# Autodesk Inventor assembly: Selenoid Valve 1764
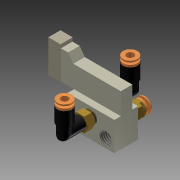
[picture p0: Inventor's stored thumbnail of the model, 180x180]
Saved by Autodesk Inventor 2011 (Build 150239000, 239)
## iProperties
Created: 2010-02
Part Number: Selenoid Valve 1764
Document SubType Name: Assembly
Designer: jgehrig
Author: jgehrig
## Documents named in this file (5)
- R:\CAD Archives\Pneumatics\Seloniod 1764\Selenoid Valve 1764.iam
- R:\CAD Archives\Pneumatics\Seloniod 1764\Selenoid Base 1764.ipt
- R:\CAD Archives\Pneumatics\Seloniod 1764\Selenoid Part 1764.ipt
- R:\CAD Archives\Pneumatics\Seloniod 1764\Pneumatic Screw 1764\Pneumatic Screw 1764.iam
- R:\CAD Archives\Pneumatics\Seloniod 1764\Pnewmatics Bend Piece 1764\Pneumatic Bend Piece 1764.iam
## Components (5 placed, 4 different names)
1. Selenoid Base 1764:1 — Flush:1, Mate:1, Flush:2, Insert:3, Insert:4, Insert:5
2. Selenoid Part 1764:1 — Flush:1, Mate:1, Flush:2, Angle:4, Angle:5
3. Pneumatic Screw 1764:1 [sub-assembly] — Insert:3
4. Pneumatic Bend Piece 1764:1 [sub-assembly] — Insert:5, Angle:4
5. Pneumatic Bend Piece 1764:2 [sub-assembly] — Insert:4, Angle:5
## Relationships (8: Insert 3, Flush 2, Angle 2, Mate 1)
- Flush:1: Selenoid Base 1764:1 ↔ Selenoid Part 1764:1
- Mate:1: Selenoid Base 1764:1 ↔ Selenoid Part 1764:1
- Flush:2: Selenoid Base 1764:1 ↔ Selenoid Part 1764:1
- Insert:3: Selenoid Base 1764:1 ↔ Pneumatic Screw 1764:1
- Insert:4: Selenoid Base 1764:1 ↔ Pneumatic Bend Piece 1764:2
- Insert:5: Selenoid Base 1764:1 ↔ Pneumatic Bend Piece 1764:1
- Angle:4: Selenoid Part 1764:1 ↔ Pneumatic Bend Piece 1764:1
- Angle:5: Selenoid Part 1764:1 ↔ Pneumatic Bend Piece 1764:2
